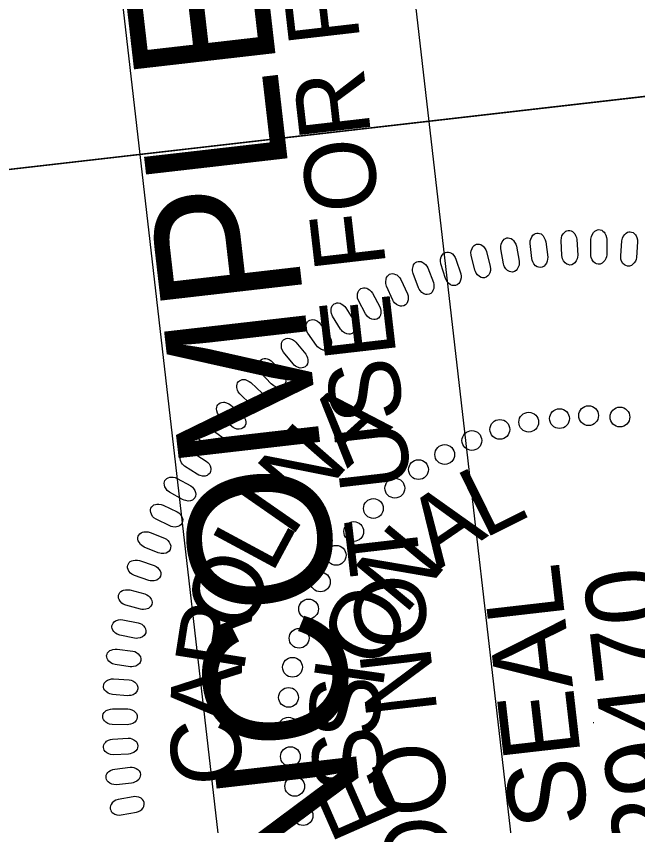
# Model space of a CAD drawing. Extents: x 474105 to 475385, y 502977 to 504774.
# Drawn here: x 474200.9 to 474251.2, y 504489.2 to 504554.8 of the extents above; entities that cross this region are included whole.
import ezdxf

# ---------------------------------------------------------------- set-up
doc = ezdxf.new("R2010")
doc.units = 0
for name, color, linetype in [('Sheet PE Seal Cell', 7, 'Continuous'), ('Sheet Plan CELL', 7, 'Continuous'), ('Sheet Sticker Incomplete CELL', 7, 'Continuous')]:
    doc.layers.add(name, color=color, linetype=linetype)

msp = doc.modelspace()

# ---------------------------------------------------------------- linework, layer by layer
at = {"layer": 'Sheet PE Seal Cell'}
msp.add_line((474247.608, 504497.584), (474247.655, 504497.589), dxfattribs=at)
for points in [[(474242.638, 504535.144), (474242.499, 504536.363), (474242.511, 504536.585), (474242.547, 504536.729), (474242.639, 504536.911), (474242.723, 504537.031), (474242.825, 504537.123), (474242.924, 504537.174), (474243.034, 504537.206), (474243.148, 504537.2), (474243.27, 504537.184), (474243.38, 504537.136), (474243.496, 504537.049), (474243.564, 504536.976), (474243.648, 504536.835), (474243.728, 504536.664), (474243.768, 504536.508), (474243.919, 504535.26), (474243.916, 504535.09), (474243.887, 504534.945), (474243.816, 504534.777), (474243.721, 504534.626), (474243.633, 504534.535), (474243.484, 504534.457), (474243.338, 504534.421), (474243.185, 504534.444), (474243.075, 504534.481), (474242.937, 504534.565), (474242.8, 504534.721), (474242.712, 504534.891), (474242.668, 504535.017)], [(474245.067, 504535.389), (474245.003, 504536.615), (474245.03, 504536.835), (474245.075, 504536.978), (474245.178, 504537.153), (474245.27, 504537.268), (474245.377, 504537.353), (474245.48, 504537.398), (474245.591, 504537.423), (474245.704, 504537.409), (474245.825, 504537.386), (474245.932, 504537.332), (474246.042, 504537.237), (474246.106, 504537.16), (474246.181, 504537.014), (474246.25, 504536.838), (474246.28, 504536.68), (474246.352, 504535.425), (474246.338, 504535.255), (474246.3, 504535.113), (474246.219, 504534.949), (474246.114, 504534.805), (474246.022, 504534.719), (474245.868, 504534.651), (474245.719, 504534.624), (474245.568, 504534.656), (474245.461, 504534.701), (474245.329, 504534.794), (474245.201, 504534.957), (474245.124, 504535.133), (474245.088, 504535.26)], [(474247.41, 504535.491), (474247.424, 504536.718), (474247.464, 504536.937), (474247.518, 504537.076), (474247.632, 504537.245), (474247.731, 504537.353), (474247.844, 504537.431), (474247.948, 504537.47), (474248.062, 504537.488), (474248.173, 504537.467), (474248.292, 504537.435), (474248.396, 504537.375), (474248.5, 504537.274), (474248.558, 504537.194), (474248.624, 504537.043), (474248.682, 504536.863), (474248.702, 504536.703), (474248.695, 504535.446), (474248.671, 504535.277), (474248.624, 504535.138), (474248.533, 504534.98), (474248.419, 504534.841), (474248.321, 504534.762), (474248.163, 504534.705), (474248.014, 504534.687), (474247.864, 504534.728), (474247.76, 504534.779), (474247.634, 504534.88), (474247.518, 504535.051), (474247.452, 504535.232), (474247.424, 504535.361)], [(474249.827, 504535.369), (474249.919, 504536.592), (474249.972, 504536.808), (474250.034, 504536.944), (474250.159, 504537.105), (474250.264, 504537.207), (474250.381, 504537.278), (474250.489, 504537.31), (474250.602, 504537.322), (474250.712, 504537.294), (474250.83, 504537.255), (474250.929, 504537.187), (474251.026, 504537.079), (474251.08, 504536.996), (474251.136, 504536.842), (474251.182, 504536.658), (474251.193, 504536.498), (474251.107, 504535.244), (474251.072, 504535.076), (474251.017, 504534.941), (474250.915, 504534.788), (474250.793, 504534.657), (474250.691, 504534.585), (474250.529, 504534.537), (474250.379, 504534.528), (474250.233, 504534.579), (474250.132, 504534.637), (474250.013, 504534.745), (474249.906, 504534.923), (474249.852, 504535.108), (474249.833, 504535.239)], [(474238.018, 504534.218), (474237.728, 504535.41), (474237.712, 504535.631), (474237.729, 504535.779), (474237.798, 504535.971), (474237.866, 504536.101), (474237.956, 504536.205), (474238.048, 504536.268), (474238.152, 504536.314), (474238.266, 504536.321), (474238.39, 504536.321), (474238.506, 504536.288), (474238.63, 504536.215), (474238.707, 504536.152), (474238.808, 504536.022), (474238.91, 504535.862), (474238.969, 504535.713), (474239.275, 504534.494), (474239.293, 504534.324), (474239.282, 504534.177), (474239.233, 504534.002), (474239.158, 504533.839), (474239.082, 504533.739), (474238.944, 504533.643), (474238.803, 504533.588), (474238.649, 504533.592), (474238.535, 504533.616), (474238.388, 504533.682), (474238.232, 504533.818), (474238.124, 504533.977), (474238.064, 504534.096)], [(474240.34, 504534.73), (474240.125, 504535.937), (474240.123, 504536.159), (474240.149, 504536.306), (474240.23, 504536.493), (474240.306, 504536.618), (474240.403, 504536.716), (474240.499, 504536.774), (474240.606, 504536.813), (474240.719, 504536.813), (474240.842, 504536.805), (474240.956, 504536.765), (474241.076, 504536.685), (474241.149, 504536.617), (474241.242, 504536.482), (474241.333, 504536.315), (474241.383, 504536.162), (474241.611, 504534.926), (474241.619, 504534.756), (474241.599, 504534.61), (474241.539, 504534.437), (474241.453, 504534.28), (474241.372, 504534.184), (474241.228, 504534.098), (474241.084, 504534.052), (474240.93, 504534.065), (474240.818, 504534.096), (474240.675, 504534.172), (474240.528, 504534.317), (474240.43, 504534.482), (474240.378, 504534.605)], [(474235.641, 504533.544), (474235.275, 504534.715), (474235.246, 504534.935), (474235.253, 504535.084), (474235.31, 504535.28), (474235.37, 504535.413), (474235.454, 504535.523), (474235.542, 504535.592), (474235.643, 504535.645), (474235.755, 504535.659), (474235.879, 504535.666), (474235.996, 504535.64), (474236.126, 504535.576), (474236.207, 504535.518), (474236.316, 504535.395), (474236.426, 504535.241), (474236.495, 504535.096), (474236.877, 504533.898), (474236.906, 504533.729), (474236.905, 504533.583), (474236.866, 504533.404), (474236.801, 504533.238), (474236.733, 504533.133), (474236.6, 504533.028), (474236.463, 504532.965), (474236.309, 504532.958), (474236.194, 504532.975), (474236.043, 504533.032), (474235.879, 504533.158), (474235.76, 504533.31), (474235.694, 504533.425)], [(474233.459, 504532.78), (474233.022, 504533.926), (474232.978, 504534.144), (474232.976, 504534.293), (474233.02, 504534.492), (474233.072, 504534.629), (474233.148, 504534.743), (474233.232, 504534.818), (474233.33, 504534.877), (474233.441, 504534.899), (474233.564, 504534.913), (474233.682, 504534.895), (474233.816, 504534.839), (474233.901, 504534.786), (474234.017, 504534.67), (474234.137, 504534.523), (474234.215, 504534.383), (474234.671, 504533.212), (474234.71, 504533.045), (474234.718, 504532.899), (474234.692, 504532.718), (474234.637, 504532.548), (474234.575, 504532.438), (474234.45, 504532.326), (474234.317, 504532.254), (474234.163, 504532.238), (474234.048, 504532.247), (474233.893, 504532.295), (474233.721, 504532.41), (474233.594, 504532.554), (474233.52, 504532.665)], [(474231.386, 504531.792), (474230.876, 504532.909), (474230.819, 504533.124), (474230.808, 504533.272), (474230.84, 504533.473), (474230.883, 504533.613), (474230.952, 504533.732), (474231.03, 504533.812), (474231.124, 504533.877), (474231.234, 504533.905), (474231.356, 504533.928), (474231.475, 504533.917), (474231.612, 504533.869), (474231.7, 504533.822), (474231.824, 504533.713), (474231.952, 504533.575), (474232.039, 504533.439), (474232.568, 504532.299), (474232.617, 504532.136), (474232.634, 504531.99), (474232.619, 504531.808), (474232.576, 504531.634), (474232.52, 504531.521), (474232.402, 504531.401), (474232.274, 504531.321), (474232.122, 504531.295), (474232.006, 504531.297), (474231.849, 504531.335), (474231.67, 504531.439), (474231.534, 504531.575), (474231.453, 504531.681)], [(474229.186, 504530.66), (474228.608, 504531.742), (474228.538, 504531.953), (474228.517, 504532.1), (474228.536, 504532.302), (474228.571, 504532.445), (474228.632, 504532.568), (474228.705, 504532.653), (474228.795, 504532.724), (474228.903, 504532.758), (474229.023, 504532.789), (474229.143, 504532.786), (474229.283, 504532.746), (474229.373, 504532.705), (474229.503, 504532.604), (474229.64, 504532.474), (474229.735, 504532.344), (474230.334, 504531.239), (474230.394, 504531.08), (474230.421, 504530.935), (474230.417, 504530.752), (474230.384, 504530.576), (474230.336, 504530.46), (474230.225, 504530.333), (474230.103, 504530.245), (474229.952, 504530.21), (474229.836, 504530.205), (474229.677, 504530.232), (474229.492, 504530.326), (474229.348, 504530.452), (474229.261, 504530.553)], [(474227.151, 504529.44), (474226.506, 504530.483), (474226.422, 504530.689), (474226.393, 504530.836), (474226.399, 504531.039), (474226.425, 504531.183), (474226.478, 504531.311), (474226.546, 504531.399), (474226.631, 504531.475), (474226.737, 504531.517), (474226.854, 504531.554), (474226.974, 504531.559), (474227.116, 504531.529), (474227.209, 504531.493), (474227.345, 504531.401), (474227.49, 504531.279), (474227.593, 504531.155), (474228.26, 504530.09), (474228.33, 504529.935), (474228.365, 504529.792), (474228.373, 504529.61), (474228.351, 504529.432), (474228.311, 504529.313), (474228.208, 504529.179), (474228.092, 504529.083), (474227.944, 504529.039), (474227.828, 504529.027), (474227.668, 504529.044), (474227.477, 504529.126), (474227.325, 504529.243), (474227.232, 504529.338)], [(474225.208, 504528.102), (474224.498, 504529.103), (474224.402, 504529.304), (474224.364, 504529.447), (474224.357, 504529.651), (474224.373, 504529.796), (474224.419, 504529.926), (474224.481, 504530.019), (474224.561, 504530.1), (474224.664, 504530.149), (474224.779, 504530.194), (474224.898, 504530.206), (474225.042, 504530.185), (474225.136, 504530.154), (474225.278, 504530.071), (474225.43, 504529.959), (474225.541, 504529.842), (474226.274, 504528.821), (474226.354, 504528.67), (474226.398, 504528.53), (474226.417, 504528.348), (474226.406, 504528.17), (474226.373, 504528.048), (474226.28, 504527.908), (474226.169, 504527.806), (474226.025, 504527.752), (474225.91, 504527.732), (474225.749, 504527.74), (474225.553, 504527.809), (474225.394, 504527.917), (474225.295, 504528.005)], [(474223.316, 504526.615), (474222.544, 504527.569), (474222.436, 504527.764), (474222.388, 504527.905), (474222.369, 504528.107), (474222.376, 504528.254), (474222.413, 504528.386), (474222.469, 504528.483), (474222.544, 504528.569), (474222.643, 504528.624), (474222.756, 504528.676), (474222.874, 504528.695), (474223.019, 504528.683), (474223.115, 504528.659), (474223.262, 504528.585), (474223.421, 504528.483), (474223.539, 504528.373), (474224.334, 504527.401), (474224.423, 504527.254), (474224.476, 504527.117), (474224.506, 504526.937), (474224.507, 504526.758), (474224.482, 504526.634), (474224.397, 504526.489), (474224.293, 504526.38), (474224.152, 504526.317), (474224.039, 504526.29), (474223.877, 504526.288), (474223.678, 504526.344), (474223.513, 504526.442), (474223.408, 504526.524)], [(474221.542, 504525.002), (474220.713, 504525.906), (474220.592, 504526.093), (474220.536, 504526.231), (474220.504, 504526.432), (474220.502, 504526.578), (474220.53, 504526.712), (474220.58, 504526.813), (474220.649, 504526.904), (474220.746, 504526.965), (474220.854, 504527.023), (474220.971, 504527.05), (474221.116, 504527.047), (474221.214, 504527.029), (474221.365, 504526.964), (474221.53, 504526.872), (474221.655, 504526.77), (474222.51, 504525.849), (474222.607, 504525.709), (474222.669, 504525.575), (474222.711, 504525.398), (474222.722, 504525.219), (474222.705, 504525.094), (474222.63, 504524.944), (474222.533, 504524.828), (474222.396, 504524.757), (474222.285, 504524.723), (474222.124, 504524.71), (474221.921, 504524.754), (474221.75, 504524.841), (474221.64, 504524.917)], [(474219.898, 504523.343), (474219.014, 504524.193), (474218.881, 504524.372), (474218.817, 504524.507), (474218.772, 504524.705), (474218.761, 504524.851), (474218.781, 504524.987), (474218.825, 504525.09), (474218.888, 504525.185), (474218.98, 504525.252), (474219.085, 504525.317), (474219.2, 504525.352), (474219.345, 504525.358), (474219.444, 504525.346), (474219.598, 504525.29), (474219.768, 504525.209), (474219.899, 504525.115), (474220.81, 504524.249), (474220.917, 504524.116), (474220.987, 504523.987), (474221.039, 504523.812), (474221.063, 504523.634), (474221.053, 504523.508), (474220.988, 504523.353), (474220.898, 504523.232), (474220.766, 504523.152), (474220.657, 504523.111), (474220.497, 504523.089), (474220.292, 504523.12), (474220.116, 504523.196), (474220.002, 504523.264)], [(474218.347, 504521.542), (474217.411, 504522.335), (474217.268, 504522.505), (474217.195, 504522.636), (474217.138, 504522.831), (474217.117, 504522.976), (474217.129, 504523.113), (474217.166, 504523.219), (474217.223, 504523.317), (474217.311, 504523.39), (474217.411, 504523.462), (474217.524, 504523.503), (474217.668, 504523.518), (474217.768, 504523.512), (474217.925, 504523.467), (474218.101, 504523.397), (474218.237, 504523.311), (474219.201, 504522.504), (474219.316, 504522.377), (474219.393, 504522.253), (474219.457, 504522.082), (474219.491, 504521.906), (474219.489, 504521.779), (474219.434, 504521.621), (474219.352, 504521.494), (474219.225, 504521.406), (474219.119, 504521.358), (474218.961, 504521.326), (474218.755, 504521.344), (474218.574, 504521.409), (474218.456, 504521.47)], [(474216.864, 504519.616), (474215.88, 504520.349), (474215.726, 504520.509), (474215.645, 504520.635), (474215.576, 504520.826), (474215.546, 504520.97), (474215.549, 504521.107), (474215.579, 504521.215), (474215.631, 504521.317), (474215.713, 504521.395), (474215.809, 504521.473), (474215.919, 504521.521), (474216.062, 504521.545), (474216.162, 504521.546), (474216.322, 504521.51), (474216.502, 504521.451), (474216.643, 504521.374), (474217.655, 504520.63), (474217.778, 504520.51), (474217.863, 504520.391), (474217.937, 504520.224), (474217.983, 504520.051), (474217.989, 504519.925), (474217.943, 504519.763), (474217.87, 504519.631), (474217.748, 504519.536), (474217.646, 504519.481), (474217.49, 504519.439), (474217.283, 504519.444), (474217.099, 504519.497), (474216.977, 504519.551)], [(474215.562, 504517.683), (474214.534, 504518.352), (474214.37, 504518.503), (474214.282, 504518.623), (474214.201, 504518.81), (474214.162, 504518.951), (474214.156, 504519.089), (474214.18, 504519.198), (474214.225, 504519.303), (474214.302, 504519.386), (474214.393, 504519.47), (474214.5, 504519.525), (474214.641, 504519.558), (474214.74, 504519.565), (474214.902, 504519.539), (474215.085, 504519.492), (474215.231, 504519.424), (474216.288, 504518.745), (474216.419, 504518.633), (474216.511, 504518.519), (474216.595, 504518.357), (474216.652, 504518.187), (474216.666, 504518.062), (474216.63, 504517.898), (474216.565, 504517.762), (474216.45, 504517.658), (474216.351, 504517.597), (474216.198, 504517.546), (474215.991, 504517.538), (474215.803, 504517.579), (474215.679, 504517.625)], [(474214.371, 504515.639), (474213.303, 504516.243), (474213.13, 504516.383), (474213.034, 504516.498), (474212.942, 504516.678), (474212.894, 504516.817), (474212.88, 504516.954), (474212.897, 504517.065), (474212.935, 504517.173), (474213.007, 504517.26), (474213.092, 504517.349), (474213.195, 504517.411), (474213.334, 504517.453), (474213.433, 504517.466), (474213.596, 504517.451), (474213.782, 504517.415), (474213.932, 504517.356), (474215.029, 504516.744), (474215.166, 504516.641), (474215.266, 504516.533), (474215.36, 504516.377), (474215.427, 504516.211), (474215.448, 504516.086), (474215.423, 504515.921), (474215.367, 504515.781), (474215.259, 504515.67), (474215.164, 504515.604), (474215.015, 504515.542), (474214.808, 504515.521), (474214.619, 504515.551), (474214.491, 504515.589)], [(474213.334, 504513.508), (474212.231, 504514.043), (474212.05, 504514.172), (474211.947, 504514.28), (474211.843, 504514.455), (474211.786, 504514.59), (474211.764, 504514.726), (474211.774, 504514.837), (474211.805, 504514.947), (474211.871, 504515.039), (474211.951, 504515.133), (474212.05, 504515.202), (474212.186, 504515.252), (474212.283, 504515.271), (474212.448, 504515.267), (474212.635, 504515.242), (474212.788, 504515.193), (474213.922, 504514.651), (474214.065, 504514.557), (474214.171, 504514.456), (474214.276, 504514.305), (474214.352, 504514.144), (474214.382, 504514.021), (474214.368, 504513.854), (474214.32, 504513.711), (474214.219, 504513.594), (474214.128, 504513.521), (474213.983, 504513.45), (474213.779, 504513.417), (474213.588, 504513.435), (474213.458, 504513.465)], [(474212.392, 504511.328), (474211.257, 504511.792), (474211.069, 504511.91), (474210.959, 504512.011), (474210.845, 504512.179), (474210.78, 504512.311), (474210.748, 504512.445), (474210.751, 504512.557), (474210.775, 504512.668), (474210.836, 504512.764), (474210.909, 504512.863), (474211.004, 504512.938), (474211.136, 504512.997), (474211.232, 504513.022), (474211.396, 504513.028), (474211.585, 504513.015), (474211.741, 504512.976), (474212.907, 504512.506), (474213.055, 504512.421), (474213.168, 504512.327), (474213.281, 504512.183), (474213.368, 504512.026), (474213.405, 504511.906), (474213.401, 504511.738), (474213.363, 504511.592), (474213.27, 504511.469), (474213.183, 504511.391), (474213.043, 504511.311), (474212.841, 504511.265), (474212.649, 504511.271), (474212.518, 504511.292)], [(474211.626, 504509.102), (474210.464, 504509.494), (474210.268, 504509.6), (474210.152, 504509.694), (474210.028, 504509.855), (474209.955, 504509.981), (474209.915, 504510.113), (474209.911, 504510.225), (474209.928, 504510.338), (474209.983, 504510.438), (474210.049, 504510.542), (474210.139, 504510.622), (474210.268, 504510.689), (474210.362, 504510.72), (474210.526, 504510.736), (474210.715, 504510.735), (474210.873, 504510.705), (474212.066, 504510.31), (474212.219, 504510.235), (474212.337, 504510.147), (474212.46, 504510.011), (474212.556, 504509.86), (474212.601, 504509.742), (474212.608, 504509.575), (474212.578, 504509.427), (474212.493, 504509.298), (474212.412, 504509.215), (474212.277, 504509.126), (474212.078, 504509.067), (474211.886, 504509.061), (474211.754, 504509.074)], [(474210.954, 504506.768), (474209.77, 504507.087), (474209.567, 504507.18), (474209.446, 504507.267), (474209.311, 504507.419), (474209.231, 504507.542), (474209.183, 504507.671), (474209.172, 504507.782), (474209.181, 504507.896), (474209.23, 504507.998), (474209.29, 504508.106), (474209.375, 504508.192), (474209.498, 504508.267), (474209.591, 504508.304), (474209.753, 504508.33), (474209.942, 504508.342), (474210.101, 504508.322), (474211.317, 504508.002), (474211.475, 504507.936), (474211.598, 504507.857), (474211.728, 504507.729), (474211.835, 504507.584), (474211.886, 504507.47), (474211.903, 504507.302), (474211.883, 504507.153), (474211.806, 504507.019), (474211.731, 504506.931), (474211.602, 504506.834), (474211.406, 504506.763), (474211.216, 504506.744), (474211.083, 504506.749)], [(474210.484, 504504.416), (474209.282, 504504.66), (474209.074, 504504.74), (474208.948, 504504.819), (474208.804, 504504.963), (474208.716, 504505.08), (474208.66, 504505.205), (474208.642, 504505.316), (474208.644, 504505.43), (474208.686, 504505.536), (474208.74, 504505.647), (474208.819, 504505.738), (474208.937, 504505.82), (474209.028, 504505.863), (474209.188, 504505.899), (474209.375, 504505.922), (474209.536, 504505.913), (474210.769, 504505.67), (474210.931, 504505.615), (474211.059, 504505.543), (474211.198, 504505.423), (474211.312, 504505.285), (474211.371, 504505.175), (474211.398, 504505.008), (474211.388, 504504.858), (474211.319, 504504.719), (474211.25, 504504.627), (474211.127, 504504.522), (474210.937, 504504.439), (474210.747, 504504.408), (474210.614, 504504.405)], [(474210.123, 504502.11), (474208.908, 504502.277), (474208.696, 504502.344), (474208.565, 504502.416), (474208.412, 504502.55), (474208.317, 504502.661), (474208.253, 504502.783), (474208.228, 504502.892), (474208.223, 504503.006), (474208.258, 504503.114), (474208.304, 504503.229), (474208.378, 504503.324), (474208.491, 504503.414), (474208.578, 504503.462), (474208.736, 504503.509), (474208.922, 504503.543), (474209.083, 504503.544), (474210.329, 504503.379), (474210.493, 504503.333), (474210.626, 504503.27), (474210.771, 504503.159), (474210.895, 504503.029), (474210.96, 504502.922), (474210.998, 504502.758), (474210.997, 504502.608), (474210.937, 504502.465), (474210.874, 504502.368), (474210.758, 504502.256), (474210.573, 504502.16), (474210.386, 504502.119), (474210.254, 504502.107)], [(474209.915, 504499.765), (474208.692, 504499.857), (474208.476, 504499.91), (474208.341, 504499.973), (474208.181, 504500.097), (474208.078, 504500.202), (474208.007, 504500.32), (474207.975, 504500.427), (474207.963, 504500.541), (474207.992, 504500.651), (474208.03, 504500.768), (474208.098, 504500.868), (474208.205, 504500.965), (474208.289, 504501.019), (474208.443, 504501.074), (474208.627, 504501.121), (474208.788, 504501.132), (474210.041, 504501.046), (474210.208, 504501.01), (474210.344, 504500.955), (474210.497, 504500.854), (474210.628, 504500.732), (474210.7, 504500.629), (474210.748, 504500.468), (474210.757, 504500.317), (474210.706, 504500.171), (474210.649, 504500.071), (474210.54, 504499.952), (474210.362, 504499.845), (474210.178, 504499.791), (474210.046, 504499.771)], [(474209.898, 504497.408), (474208.671, 504497.423), (474208.452, 504497.463), (474208.314, 504497.517), (474208.145, 504497.631), (474208.036, 504497.729), (474207.958, 504497.843), (474207.919, 504497.947), (474207.901, 504498.06), (474207.923, 504498.172), (474207.953, 504498.29), (474208.015, 504498.395), (474208.116, 504498.498), (474208.196, 504498.557), (474208.346, 504498.623), (474208.527, 504498.68), (474208.686, 504498.701), (474209.943, 504498.694), (474210.112, 504498.669), (474210.251, 504498.623), (474210.41, 504498.532), (474210.548, 504498.418), (474210.627, 504498.32), (474210.685, 504498.162), (474210.703, 504498.012), (474210.661, 504497.863), (474210.611, 504497.759), (474210.509, 504497.633), (474210.338, 504497.515), (474210.158, 504497.451), (474210.028, 504497.422)], [(474209.994, 504495.042), (474208.768, 504494.979), (474208.547, 504495.005), (474208.406, 504495.05), (474208.23, 504495.153), (474208.116, 504495.245), (474208.03, 504495.353), (474207.985, 504495.455), (474207.96, 504495.566), (474207.974, 504495.679), (474207.998, 504495.8), (474208.052, 504495.908), (474208.146, 504496.017), (474208.223, 504496.081), (474208.369, 504496.156), (474208.545, 504496.225), (474208.703, 504496.256), (474209.958, 504496.327), (474210.128, 504496.314), (474210.27, 504496.276), (474210.434, 504496.194), (474210.579, 504496.09), (474210.664, 504495.997), (474210.732, 504495.843), (474210.759, 504495.694), (474210.727, 504495.543), (474210.682, 504495.436), (474210.589, 504495.304), (474210.426, 504495.176), (474210.251, 504495.1), (474210.122, 504495.063)], [(474210.237, 504492.695), (474209.018, 504492.555), (474208.796, 504492.567), (474208.651, 504492.604), (474208.47, 504492.696), (474208.35, 504492.78), (474208.258, 504492.882), (474208.206, 504492.981), (474208.174, 504493.091), (474208.181, 504493.204), (474208.197, 504493.327), (474208.244, 504493.437), (474208.331, 504493.552), (474208.404, 504493.621), (474208.545, 504493.705), (474208.717, 504493.785), (474208.873, 504493.825), (474210.12, 504493.976), (474210.291, 504493.973), (474210.435, 504493.944), (474210.603, 504493.873), (474210.756, 504493.778), (474210.845, 504493.69), (474210.923, 504493.541), (474210.959, 504493.395), (474210.937, 504493.242), (474210.899, 504493.132), (474210.815, 504492.994), (474210.66, 504492.856), (474210.489, 504492.769), (474210.364, 504492.725)], [(474210.373, 504491.588), (474209.165, 504491.372), (474208.956, 504491.296), (474208.828, 504491.221), (474208.68, 504491.08), (474208.589, 504490.965), (474208.531, 504490.841), (474208.51, 504490.731), (474208.51, 504490.617), (474208.55, 504490.51), (474208.6, 504490.398), (474208.677, 504490.305), (474208.794, 504490.22), (474208.883, 504490.175), (474209.042, 504490.135), (474209.229, 504490.107), (474209.39, 504490.114), (474210.629, 504490.328), (474210.791, 504490.379), (474210.921, 504490.448), (474211.062, 504490.564), (474211.18, 504490.7), (474211.242, 504490.809), (474211.273, 504490.975), (474211.266, 504491.125), (474211.2, 504491.265), (474211.133, 504491.36), (474211.012, 504491.467), (474210.825, 504491.555), (474210.636, 504491.589), (474210.503, 504491.596)]]:
    msp.add_lwpolyline(points, close=True, dxfattribs=at)
for centre in [(474247.23, 504522.432), (474242.385, 504521.906), (474244.878, 504522.192), (474249.769, 504522.322), (474240.046, 504521.318), (474237.784, 504520.418), (474235.588, 504519.284), (474233.464, 504518.062), (474231.551, 504516.56), (474229.814, 504514.919), (474228.224, 504513.053), (474226.8, 504511.127), (474225.523, 504508.977), (474224.571, 504506.784), (474223.801, 504504.412), (474223.267, 504502.066), (474222.945, 504499.625), (474222.94, 504497.22), (474223.093, 504494.833), (474223.449, 504492.429), (474224.121, 504490.062)]:
    msp.add_circle(centre, 0.801, dxfattribs=at)
at = {"layer": 'Sheet Plan CELL'}
msp.add_line((474178.408, 504539.835), (474290.134, 504552.684), dxfattribs=at)
for points in [[(474178.408, 504539.835), (474166.984, 504639.168), (474278.759, 504652.022), (474290.186, 504552.677)], [(474189.828, 504440.439), (474178.408, 504539.835), (474290.186, 504552.677), (474301.579, 504453.291)]]:
    msp.add_lwpolyline(points, close=True, dxfattribs=at)
at = {"layer": 'Sheet Sticker Incomplete CELL'}
msp.add_lwpolyline([(474242.68, 504473.236), (474219.333, 504470.554), (474202.555, 504616.593), (474225.902, 504619.275)], close=True, dxfattribs=at)

# ---------------------------------------------------------------- texts
at = {"layer": 'Sheet PE Seal Cell'}
for s, height, rotation, p in [('A', 5.669, 42.22666, (474227.696, 504518.116)), ('N', 5.669, 48.71602, (474224.319, 504514.387)), ('L', 5.669, 26.3847, (474238.749, 504512.449)), ('I', 5.669, 55.20538, (474223.114, 504512.431)), ('A', 5.669, 34.32449, (474235.022, 504509.883)), ('L', 5.669, 61.69474, (474221.581, 504509.544)), ('N', 5.669, 50.20409, (474232.343, 504506.216)), ('O', 5.669, 68.18409, (474219.607, 504504.553)), ('SEAL', 6.2363, 96.5352, (474247.242, 504489.447)), ('29470', 6.2363, 96.5352, (474255.606, 504487.417)), ('O', 5.669, 66.08368, (474230.546, 504501.67)), ('R', 5.669, 81.1628, (474219.294, 504501.543)), ('A', 5.669, 87.65216, (474218.985, 504497.273)), ('I', 5.669, 81.96328, (474230.546, 504500.156)), ('S', 5.669, 89.90307, (474230.353, 504496.309)), ('C', 5.669, 94.14152, (474219.3, 504492.704)), ('S', 5.669, 97.84287, (474230.894, 504492.485)), ('E', 5.669, 113.72247, (474232.163, 504489.845))]:
    msp.add_text(s, height=height, rotation=rotation, dxfattribs=at).set_placement(p)
at = {"layer": 'Sheet Sticker Incomplete CELL'}
for s, height, p in [('INCOMPLETE PLANS', 11.52, (474230.035, 504480.792)), ('DO NOT USE FOR R/W ACQUISITION', 5.76, (474236.568, 504484.814))]:
    msp.add_text(s, height=height, rotation=96.55384, dxfattribs=at).set_placement(p)

doc.saveas('drawing.dxf')
